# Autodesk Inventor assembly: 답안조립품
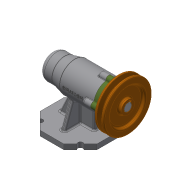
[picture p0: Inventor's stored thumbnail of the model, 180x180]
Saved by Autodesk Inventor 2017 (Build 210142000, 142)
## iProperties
Created: 2019-12
Part Number: 답안조립품
Document SubType Name: Assembly
Designer: 5-08-le
Author: 5-08-le
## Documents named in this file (12)
- C:\Users\5-08-le\Desktop\491204V1032\답안조립품.iam
- C:\Users\5-08-le\Desktop\491204V1032\본체.ipt
- C:\Users\5-08-le\Desktop\491204V1032\축.ipt
- C:\Users\5-08-le\Desktop\491204V1032\키 5 x 5 x 16.ipt
- C:\Users\5-08-le\Desktop\491204V1032\멈춤나사 M3.ipt
- C:\Users\5-08-le\Desktop\491204V1032\베어링 6004.ipt
- C:\Users\5-08-le\Desktop\491204V1032\어댑터슬리브.ipt
- C:\Users\5-08-le\Desktop\491204V1032\볼트 M4.ipt
- C:\Users\5-08-le\Desktop\491204V1032\베어링 51202.ipt
- C:\Users\5-08-le\Desktop\491204V1032\커버.ipt
- C:\Users\5-08-le\Desktop\491204V1032\오일 실.ipt
- C:\Users\5-08-le\Desktop\491204V1032\V벨트풀리.ipt
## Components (1 placed, 1 different names)
1. V벨트풀리:1
